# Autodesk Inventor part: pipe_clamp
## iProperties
Shininess: 64.0
Length Units: 11269
Angle Units: 11279
Time Units: 11290
Mass Units: 11283
Length Display Precision: 3
Angle Display Precision: 2
Compacted: True
Part Number: pipe_clamp
Document SubType Name: Modeling
Created: 2004-07
Designer: Peter
Manufacturer: Standard
Standards Organization: Custom
Density: 0.0
Volumn: 0.0
Area: 0.0
PropertySet Name: Model Information
Control State: 0
Master: False
Checked Out: False
Author: Peter
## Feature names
1. Revolution3
2. Extrusion1
3. Hole5
4. Hole6
5. Hole7
6. Hole8
7. Extrusion2
8. Extrusion3
9. Hole11
10. Hole12
11. Hole13
12. Hole14
